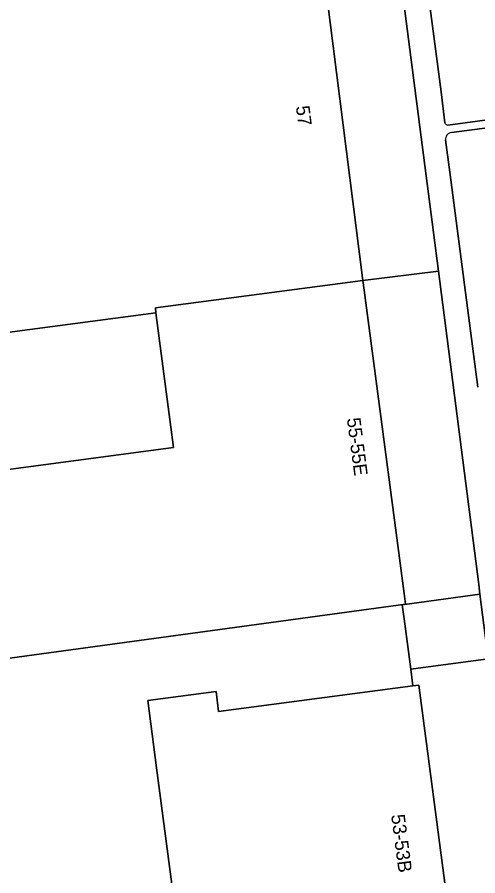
# Model space of a CAD drawing. Extents: x 160554 to 161248, y 385329 to 386506.
# Drawn here: x 161065.9 to 161099.8, y 385731.1 to 385794.2 of the extents above; entities that cross this region are included whole.
import ezdxf

# ---------------------------------------------------------------- set-up
doc = ezdxf.new("R2010")
doc.units = 0
for name, color, linetype in [('IMGEO_Erf', 7, 'Continuous'), ('IMGEO_Groenvoorziening', 7, 'Continuous'), ('IMGEO_Pand', 7, 'Continuous'), ('IMGEO_Pand_nummerreeks', 7, 'Continuous'), ('IMGEO_Parkeervlak_open', 7, 'Continuous'), ('IMGEO_Rijbaan_lokaal_open', 7, 'Continuous'), ('IMGEO_Voetpad_open', 7, 'Continuous')]:
    doc.layers.add(name, color=color, linetype=linetype)

msp = doc.modelspace()

# ---------------------------------------------------------------- linework, layer by layer
at = {"layer": 'IMGEO_Erf'}
for points in [[(161077.573, 385728.065), (161076.135, 385739.04), (161075.485, 385743.997), (161080.504, 385744.655), (161080.694, 385743.204), (161094.985, 385745.077), (161094.826, 385746.297), (161094.343, 385750), (161094.207, 385751.045), (161099.92, 385751.819), (161099.829, 385752.532), (161096.873, 385775.58), (161091.316, 385774.876), (161091.407, 385774.182), (161094.334, 385751.863), (161094.436, 385751.08), (161063.317, 385746.837)], [(161038.492, 385757.432), (161077.384, 385762.597), (161076.078, 385772.498), (161056.219, 385769.879)]]:
    msp.add_lwpolyline(points, dxfattribs=at)
at = {"layer": 'IMGEO_Groenvoorziening'}
for points in [[(161101.206, 385786.207), (161097.823, 385785.757)], [(161097.389, 385785.218), (161097.713, 385782.852), (161099.765, 385767.038)]]:
    msp.add_lwpolyline(points, dxfattribs=at)
msp.add_arc((161097.873, 385785.273), 0.487, 95.86829, 186.45004, dxfattribs=at)
at = {"layer": 'IMGEO_Pand'}
for points in [[(161076.078, 385772.498), (161076.047, 385772.874), (161091.316, 385774.876), (161088.156, 385799.689), (161087.153, 385799.563), (161052.902, 385795.197), (161055.868, 385772.603), (161056.153, 385770.395), (161056.219, 385769.879)], [(161076.078, 385772.498), (161077.384, 385762.597), (161038.492, 385757.432), (161038.201, 385757.455), (161036.601, 385743.194), (161056.279, 385745.877), (161063.317, 385746.837), (161094.436, 385751.08), (161094.334, 385751.863), (161091.407, 385774.182), (161091.316, 385774.876), (161076.047, 385772.874)], [(161098.665, 385720.503), (161095.436, 385745.136), (161094.985, 385745.077), (161080.694, 385743.204), (161080.504, 385744.655), (161075.485, 385743.997), (161076.135, 385739.04), (161077.573, 385728.065), (161066.743, 385726.646), (161068.084, 385716.495)]]:
    msp.add_lwpolyline(points, close=True, dxfattribs=at)
at = {"layer": 'IMGEO_Parkeervlak_open'}
for points in [[(161096.053, 385796.416), (161097.068, 385788.754), (161097.33, 385786.485)], [(161097.565, 385786.316), (161101.916, 385786.906)]]:
    msp.add_lwpolyline(points, dxfattribs=at)
msp.add_arc((161097.586, 385786.593), 0.278, 202.86778, 265.6887, dxfattribs=at)
at = {"layer": 'IMGEO_Rijbaan_lokaal_open'}
msp.add_lwpolyline([(161099.92, 385751.819), (161094.207, 385751.045), (161094.343, 385750), (161094.826, 385746.297), (161100.53, 385747.059)], close=True, dxfattribs=at)
at = {"layer": 'IMGEO_Voetpad_open'}
for points in [[(161091.644, 385839.67), (161090.577, 385836.855), (161089.36, 385832.82), (161089.359, 385832.428), (161093.052, 385804.928), (161093.658, 385800.418), (161096.873, 385775.58), (161099.829, 385752.532), (161099.92, 385751.819), (161100.53, 385747.059), (161103.849, 385721.182), (161103.528, 385716.968), (161104.544, 385708.871), (161105.47, 385701.933), (161107.028, 385690.183), (161107.754, 385684.63), (161108.994, 385675.141), (161109.438, 385671.741), (161109.961, 385671.806), (161111.073, 385663.16), (161112.38, 385652.994), (161113.833, 385641.697), (161115.047, 385634.843), (161117.413, 385635.068)], [(161097.33, 385786.485), (161097.068, 385788.754), (161096.053, 385796.416)], [(161101.916, 385786.906), (161097.565, 385786.316)], [(161097.823, 385785.757), (161101.206, 385786.207)], [(161099.765, 385767.038), (161097.713, 385782.852), (161097.389, 385785.218)]]:
    msp.add_lwpolyline(points, dxfattribs=at)
for points in [[(161093.658, 385800.418), (161088.156, 385799.689), (161091.316, 385774.876), (161096.873, 385775.58)], [(161100.53, 385747.059), (161094.826, 385746.297), (161094.985, 385745.077), (161095.436, 385745.136), (161098.665, 385720.503), (161103.849, 385721.182)]]:
    msp.add_lwpolyline(points, close=True, dxfattribs=at)
for centre, radius, start, end in [((161097.586, 385786.593), 0.278, 202.86778, 265.6887), ((161097.873, 385785.273), 0.487, 95.86829, 186.45004)]:
    msp.add_arc(centre, radius, start, end, dxfattribs=at)

# ---------------------------------------------------------------- texts
at = {"layer": 'IMGEO_Pand_nummerreeks'}
for s, rotation, p in [('57', 277.2577, (161086.377, 385787.687)), ('55-55E', 277.47135, (161090.124, 385764.74)), ('53-53B', 277.468, (161093.382, 385735.573))]:
    msp.add_text(s, height=1, rotation=rotation, dxfattribs=at).set_placement(p)

doc.saveas('drawing.dxf')
